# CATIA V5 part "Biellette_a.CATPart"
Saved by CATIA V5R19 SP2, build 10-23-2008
Part number: Biellette_a
Bounding box of the stored display mesh (mm): x -29 to -17, y -304 to -284, z -150.824 to 90
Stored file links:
  G:\EU_thinkMotion\CFAO_2010\MMS_groupe3\MMS_groupe3\pmayet\pmayet_assemblage_animation\pmayet_assemblage_animation\Biellette_a.CATPart
  G:\EU_thinkMotion\CFAO_2010\MMS_groupe3\MMS_groupe3\pmayet\pmayet_assemblage_animation\pmayet_assemblage_animation\pmayet_assemblage_animation.CATProduct
  G:\EU_thinkMotion\CFAO_2010\MMS_groupe3\MMS_groupe3\pmayet\pmayet_assemblage_animation\pmayet_assemblage_animation\Squelette_biellette_a.CATPart
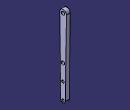
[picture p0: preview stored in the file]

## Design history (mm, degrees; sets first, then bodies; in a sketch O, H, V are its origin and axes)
Parameters
  Epaisseur_biellette_a = 6 mm
  Rayon_trou = 5 mm
  Rayon_trou_biellete = 3.5 mm
  Rayon_trou_barre_de_liaison = 4 mm
Set1
  Plane1: linked copy from another document
  Point1 "Point.12_biellete_a": linked copy from another document
  Plane2: linked copy from another document
  Point2 "Point.15_biellete_a": linked copy from another document
  Plane3: linked copy from another document
  Point3 "Point.13_biellete_a": linked copy from another document
  Point4 "Point.14_biellete_a": linked copy from another document
Body1 (main body)
  Sketch1 on Plane1, origin (-23, 0, 0), H (0, -1, 0), V (0, 0, 1)
    arc A1 centre (294, 80) radius 10 from (304, 80) to (284, 80) ccw
    point P1 (294, 80)
    point P2 (304, 80)
    point P3 (284, 80)
    reference projected point E1 (294, 80) from Point1
    reference intersected line E2 through (0, 80) direction (1, 0) from Plane2
    reference intersected line E3 through (0, 80) direction (1, 0) from Plane2
    arc A2 centre (294, -144) radius 7 from (287, -144) to (301, -144) ccw
    point P4 (294, -144)
    point P5 (287, -144)
    point P6 (301, -144)
    reference projected point E4 (294, -144) from Point2
    reference intersected line E5 through (0, -144) direction (1, 0) from Plane3
    reference intersected line E6 through (0, -144) direction (1, 0) from Plane3
    line L1 (284, 80) -> (287, -144)
    point P7 (284, 80)
    point P8 (287, -144)
    line L2 (304, 80) -> (301, -144)
    point P9 (304, 80)
    point P10 (301, -144)
    radius A1 = 10 {= Rayon_trou *2}
    distance E2 P2 = 0
    distance E3 P3 = 0
    radius A2 = 7 {= Rayon_trou_biellete *2}
    distance E5 P5 = 0
    distance P6 E6 = 0
    distance P2 P9 = 0
    distance P10 P6 = 0
    distance P3 P7 = 0
    distance P8 P5 = 0
    coincidence: P1 E1, P4 E4
  Pad1: profile Sketch1, direction (-1, 0, 0), length 6 {= Epaisseur_biellette_a}, mirrored extent
  Sketch2 on Plane1, origin (-23, 0, 0), H (0, -1, 0), V (0, 0, 1)
    circle A1 centre (294, 80) radius 5
    point P1 (294, 80)
    reference projected point E1 (294, 80) from Point1
    distance A1 P1 = 5 {= Rayon_trou}
    coincidence: P1 E1
  Pocket1: profile Sketch2, direction (1, 0, 0), length 6 {= Epaisseur_biellette_a}, mirrored extent
  Sketch3 on Plane1, origin (-23, 0, 0), H (0, -1, 0), V (0, 0, 1)
    circle A1 centre (294, -48) radius 5
    point P1 (294, -48)
    reference projected point E1 (294, -48) from Point3
    distance A1 P1 = 5 {= Rayon_trou}
    coincidence: P1 E1
  Pocket2: profile Sketch3, direction (1, 0, 0), length 6 {= Epaisseur_biellette_a}, mirrored extent
  Sketch4 on Plane1, origin (-23, 0, 0), H (0, -1, 0), V (0, 0, 1)
    circle A1 centre (294, -96) radius 4
    point P1 (294, -96)
    reference projected point E1 (294, -96) from Point4
    distance P1 A1 = 4 {= Rayon_trou_barre_de_liaison}
    coincidence: P1 E1
  Pocket3: profile Sketch4, direction (1, 0, 0), length 6 {= Epaisseur_biellette_a}, mirrored extent
  Sketch5 on Plane1, origin (-23, 0, 0), H (0, -1, 0), V (0, 0, 1)
    circle A1 centre (294, -144) radius 3.5
    point P1 (294, -144)
    reference projected point E1 (294, -144) from Point2
    distance P1 A1 = 3.5 {= Rayon_trou_biellete}
    coincidence: E1 P1
  Pocket4: profile Sketch5, direction (1, 0, 0), length 6 {= Epaisseur_biellette_a}, mirrored extent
